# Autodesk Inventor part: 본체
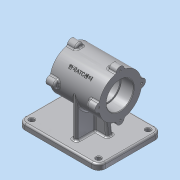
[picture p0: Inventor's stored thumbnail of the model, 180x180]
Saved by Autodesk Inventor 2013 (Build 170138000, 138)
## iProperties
Created: 2015-12
Part Number: 본체
Material: 알루미늄 6061
Document SubType Name: Modeling
Designer: dgall
Density: 2.71 g/cm^3
Mass: 1160.78 g
Surface Area: 819.071 cm^2
Volume: 428.332 cm^3
Author: dgall
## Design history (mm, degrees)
sketch "스케치1"
  geometry: L1 (-70, 55)-(70, 55); L2 (70, 55)-(70, -55); L3 (70, -55)-(-70, -55); L4 (-70, -55)-(-70, 55); 1 further point
  constraints: 8 end point, 2 parallel, 1 horizontal, 1 perpendicular
  dimensions: "d0" = 140 distance of L1.start L1.end; "d2" = 110 distance of L1.end L2.end; "d3" = 70 distance from line of point (0, 0) L4; "d4" = 55 distance from line of point (0, 0) L3
extrude "돌출1" new body sketch "스케치1" distance "d5" = 10; taper "d6" = 0 deg
node "작업 평면1"
sketch "스케치2"
  geometry: L1 (70, 55)-(-70, 55) reference; L2 (-70, 55)-(-70, -55) reference; L3 (-70, -55)-(70, -55) reference; L4 (70, -55)-(70, 55) reference; L5 (-70, 0)-(70, 0); L6 (-32.5, 37)-(52.5, 37); L7 (52.5, 37)-(52.5, 23.5); L8 (52.5, 23.5)-(30.5, 23.5); L9 (30.5, 23.5)-(30.5, 21); L10 (30.5, 21)-(-10.5, 21); L11 (-10.5, 21)-(-10.5, 23.5); L12 (-32.5, 37)-(-32.5, 23.5); L13 (-32.5, 23.5)-(-10.5, 23.5); 1 further point
  constraints: 18 end point, 4 parallel, 4 perpendicular, 2 midpoint
  dimensions: "d8" = 42 diameter of L10 L5; "d9" = 74 diameter of L6 L5; "d11" = 47 diameter of L8 L5; "d12" = 47 diameter of L13 L5; "d13" = 37.5 distance between parallel lines of L2 L12; "d14" = 85 distance between parallel lines of L7 L12; "d15" = 22 distance between parallel lines of L11 L12; "d16" = 41 distance between parallel lines of L9 L11
revolve "회전1" sketch "스케치2" stored, may be unused: angle "d17" = 90 deg
node "작업 평면2"
sketch "스케치3"
  geometry: L1 (-80, -55)-(-80, 55) reference; L2 (-80, -55)-(-70, -55) reference; L3 (-70, 55)-(-70, -55) reference; L4 (-80, 55)-(-70, 55) reference; L5 (0, -37)-(-70, -37); L6 (0, 37)-(-70, 37); C1 r 23.5 at (0, 0) reference; A1 r 37 centre (0, 0) between (0, 37) and (0, -37) reference; 1 further point
  constraints: 4 end point, 2 parallel, 2 point on circle, 2 point on line, 2 tangent
extrude "돌출2" join sketch "스케치3" stored distance "d19" = 8; taper "d20" = 0 deg
sketch "스케치4"
  geometry: L1 (32.5, 43)-(-52.5, 43) reference; L2 (-70, 10)-(70, 10) reference; L3 (10.948, 43)-(15, 10); L4 (-30.948, 43)-(-35, 10); L5 (-14, 10)-(-14, 80) reference; 1 further point
  constraints: 4 end point, 4 point on line
  dimensions: "d21" = 97 deg angle of L2 L3; "d22" = 29 distance from line of L5 L3.end; "d23" = 97 deg angle of L2 L4; "d24" = 50 distance of L3.end L4.end
feature "리브1" dims "d25" = 1, "d26" = 10, "d27" = 0, "d28" = 0, "d29" = 1, "d30" = 1
feature "리브2" dims "d31" = 1, "d32" = 10, "d33" = 0, "d34" = 0, "d35" = 1, "d36" = 1
fillet "모깎기1" dims "d52" = 3
fillet "모깎기2" dims "d53" = 3
fillet "모깎기3" dims "d54" = 3
fillet "모깎기4" dims "d55" = 3
fillet "모깎기5" dims "d56" = 12
fillet "모깎기6" dims "d57" = 3
sketch "스케치7" dims "d66" = 10, "d73" = 10, "d80" = 10
  geometry: L1 (58, -52)-(-58, -52) reference; L2 (67, 43)-(67, -43) reference; L3 (-58, 52)-(58, 52) reference; L4 (58, 55)-(-58, 55) reference; L5 (-70, 43)-(-70, -43) reference; C1 r 4 at (-58, 43); C2 r 4 at (58, 43); C3 r 4 at (58, -43); C4 r 4 at (-58, -43); 1 further point
  constraints: 4 centre point, 2 horizontal, 1 vertical, 6 other
  dimensions: "d58" = 12 distance from line of L4 C1.centre; "d59" = 12 distance from line of L5 C1.centre; "d60" = 8 diameter of C1; "d63" = 116 distance of C1.centre C2.centre; "d70" = 86 distance of C2.centre C3.centre; "d77" = 116 distance of C3.centre C4.centre
extrude "돌출5" cut sketch "스케치7" stored distance "d82" = 15; taper "d83" = 0 deg
chamfer "모따기1" distance "d84" = 1; stored, may be unused: second distance "d85" = 2, angle "d86" = 45 deg
node "작업 평면3"
node "작업 평면5"
sketch "스케치9"
  geometry: L1 (80, 43)-(80, -43) reference; C1 r 7 at (0, 37); 2 further points
  constraints: 1 centre point, 1 vertical alignment, 1 other
  dimensions: "d98" = 14 diameter of C1; "d100" = 80 distance from line of L1 C1.centre
extrude "돌출6" join sketch "스케치9" distance "d101" = 15; taper "d102" = 0 deg
fillet "모깎기7" dims "d103" = 3
sketch "스케치10"
  geometry: L1 (-80, -43)-(-80, 43) reference; C1 r 7 at (0, -37); 2 further points
  constraints: 1 centre point, 1 vertical alignment, 1 other
  dimensions: "d107" = 14 diameter of C1; "d109" = 80 distance from line of L1 C1.centre
extrude "돌출7" join sketch "스케치10" distance "d110" = 15; taper "d111" = 0 deg
fillet "모깎기8" dims "d112" = 3
sketch "스케치11"
  geometry: C1 r 23.5 at (0, -37) reference; C2 r 37 at (0, -37); A1 r 7 centre (0, 0) between (6.889, 1.239) and (-6.889, 1.239) reference; A2 r 7 centre (-37, -37) between (-38.239, -30.111) and (-38.239, -43.889) reference; A3 r 7 centre (0, -74) between (-6.889, -75.239) and (6.889, -75.239) reference; A4 r 7 centre (37, -37) between (38.239, -43.889) and (38.239, -30.111) reference; 1 further point
  constraints: 1 centre point, 1 coincident
  dimensions: "d116" = 74 diameter of C2
hole "구멍1" sketch "스케치11" at (-37, -37), (0, 0), (37, -37), (0, -74) diameter "d118" = 3.242; stored, may be unused: countersink angle "d122" = 90 deg, drill point angle "d124" = 118 deg; dims "d119" = 9, "d120" = 4, "d121" = 2, "d123" = 11
sketch "스케치12"
  geometry: A1 r 7 centre (0, 74) between (6.889, 75.239) and (-6.889, 75.239) reference; A2 r 7 centre (-37, 37) between (-38.239, 43.889) and (-38.239, 30.111) reference; A3 r 7 centre (0, 0) between (-6.889, -1.239) and (6.889, -1.239) reference; A4 r 7 centre (37, 37) between (38.239, 30.111) and (38.239, 43.889) reference; 1 further point
hole "구멍2" sketch "스케치12" at (0, 74), (37, 37), (0, 0), (-37, 37) diameter "d125" = 3.242; stored, may be unused: countersink angle "d129" = 90 deg, drill point angle "d131" = 118 deg; dims "d126" = 9, "d127" = 4, "d128" = 2, "d130" = 11
node "작업 평면6"
node "작업 평면7"
node "작업 평면8"
sketch "스케치14"
  geometry: L1 (-20.739, 3.002)-(20.739, 3.002); L2 (20.739, 3.002)-(20.739, -3.002); L3 (20.739, -3.002)-(-20.739, -3.002); L4 (-20.739, -3.002)-(-20.739, 3.002); L5 (-20.739, 0)-(20.739, 0); L6 (0, 3.002)-(0, -3.002); L7 (42.5, -18.921)-(42.5, 18.921) reference; L8 (-42.5, 37)-(42.5, 37) reference; 1 further point
  constraints: 4 end point, 4 midpoint, 2 other
  dimensions: "d134" = 42.5 distance between parallel lines of L7 L6; "d135" = 37 distance between parallel lines of L8 L5
extrude "돌출8" join sketch "스케치14" stored distance "d136" = 15; taper "d137" = 0 deg
fillet "모깎기9" dims "d138" = 0.3
fillet "모깎기10" dims "d139" = 3
chamfer "모따기2" distance "d140" = 1; stored, may be unused: second distance "d141" = 2, angle "d142" = 45 deg
node "솔리드1"
pattern_circular "원형 패턴3" dims angle "d105" = 360 deg
pattern_circular "원형 패턴4" dims angle "d114" = 360 deg
node "투영된 루프1"
node "투영된 루프2"
node "투영된 루프3"
other parameters: "d18" = -42.5, "d87" = -43, "d133" = -0.5
